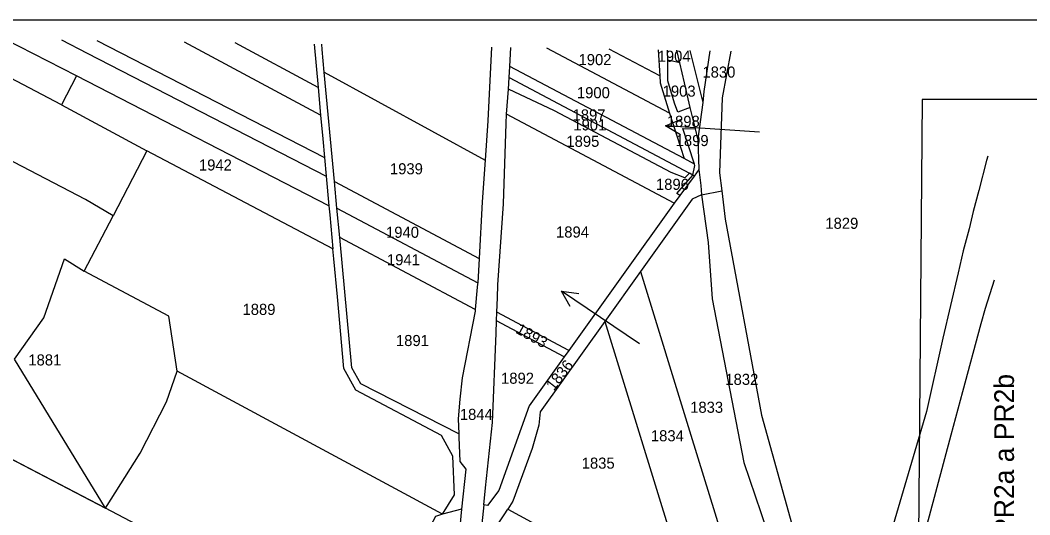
# Model space of a CAD drawing. Extents: x -584305 to -582773, y -1166873 to -1164754.
# Drawn here: x -583983 to -583345, y -1165085 to -1164773 of the extents above; entities that cross this region are included whole.
import ezdxf

# ---------------------------------------------------------------- set-up
doc = ezdxf.new("R2010")
doc.units = 0
for name, color, linetype in [('37', 7, 'Continuous'), ('_Rám HC11-R', 7, 'Continuous'), ('Hranice parcel', 7, 'Continuous'), ('Parcelní čísla', 7, 'Continuous')]:
    doc.layers.add(name, color=color, linetype=linetype)

msp = doc.modelspace()

# ---------------------------------------------------------------- linework, layer by layer
at = {"layer": '37'}
for p, q in [((-583515.54, -1164843.77), (-583574.89, -1164839.89)), ((-583591.27, -1164977.57), (-583640.58, -1164944.31))]:
    msp.add_line(p, q, dxfattribs=at)
for points in [[(-583565.32, -1164845.48), (-583574.89, -1164839.89), (-583564.68, -1164835.59)], [(-583635.14, -1164953.96), (-583640.58, -1164944.31), (-583629.59, -1164945.74)]]:
    msp.add_lwpolyline(points, dxfattribs=at)
at = {"layer": '_Rám HC11-R'}
for p, q in [((-583412.61, -1164823.12), (-583417.05, -1165365.82)), ((-583171.08, -1164823.12), (-583412.61, -1164823.12))]:
    msp.add_line(p, q, dxfattribs=at)
msp.add_lwpolyline([(-582820.03, -1166873.12), (-582820.03, -1164773.12), (-584305.03, -1164773.12), (-584305.03, -1166873.12), (-582820.03, -1166873.12)], dxfattribs=at)
msp.add_lwpolyline([(-583928.98, -1165081.35), (-583986.49, -1164987.28), (-583967.99, -1164961.13), (-583954.85, -1164923.82), (-583942.36, -1164931.66), (-583924.13, -1164896.6), (-583941.58, -1164886.27), (-584101.83, -1164802.98), (-584094.81, -1164829.69), (-584009.27, -1164870.93), (-583995.35, -1164891.63), (-584020.43, -1164938.66), (-584028.48, -1164951.62), (-584035.7, -1164958.26), (-584055.06, -1164973.28), (-584042.99, -1165013.09), (-584037.3, -1165024.95)], close=True, dxfattribs=at)
at = {"layer": 'Hranice parcel'}
for p, q in [((-583956.67, -1164826.46), (-584037.5, -1164784.25)), ((-583947.23, -1164808.23), (-583992.46, -1164785)), ((-583797.07, -1164788.27), (-583794.55, -1164815.59)), ((-583673.36, -1164802.36), (-583672.59, -1164790.35)), ((-583572.27, -1164831.74), (-583650, -1164790.72)), ((-583578.48, -1164808.32), (-583610.56, -1164791.38)), ((-583573.5, -1164798.45), (-583573.59, -1164792)), ((-583565.79, -1164800.08), (-583567.76, -1164792.1)), ((-583559.42, -1164792.24), (-583551.21, -1164825.14)), ((-583565.79, -1164800.08), (-583573.5, -1164798.45)), ((-583790.62, -1164805.87), (-583688.95, -1164861.53)), ((-583784.14, -1164875.08), (-583790.62, -1164805.87)), ((-583673.81, -1164809.27), (-583673.36, -1164802.36)), ((-583563.17, -1164860.53), (-583673.36, -1164802.36)), ((-583947.23, -1164808.23), (-583956.67, -1164826.46)), ((-583787.65, -1164890.27), (-583947.23, -1164808.23)), ((-583674.2, -1164816.62), (-583673.81, -1164809.27)), ((-583673.81, -1164809.27), (-583559.73, -1164869.75)), ((-583794.55, -1164815.59), (-583792.92, -1164833.12)), ((-583675.3, -1164832.56), (-583674.2, -1164816.62)), ((-583551.21, -1164825.14), (-583554.55, -1164848.01)), ((-583956.67, -1164826.46), (-583902.79, -1164855.56)), ((-583556.01, -1164841.8), (-583559.26, -1164828.28)), ((-583569.45, -1164888.74), (-583675.3, -1164832.56)), ((-583572.27, -1164831.74), (-583563.17, -1164860.53)), ((-583554.55, -1164848.01), (-583556.01, -1164841.8)), ((-583554.55, -1164848.01), (-583553.72, -1164867.31)), ((-583902.79, -1164855.56), (-583924.13, -1164896.6)), ((-583785.12, -1164917.52), (-583902.79, -1164855.56)), ((-583790.48, -1164859.88), (-583789.39, -1164871.59)), ((-583556.62, -1164863.99), (-583563.17, -1164860.53)), ((-583557.54, -1164871.02), (-583559.73, -1164869.75)), ((-583553.72, -1164867.31), (-583556.82, -1164871.54)), ((-583789.39, -1164871.59), (-583787.65, -1164890.27)), ((-583784.14, -1164875.08), (-583692.74, -1164923.53)), ((-583782.59, -1164891.76), (-583784.14, -1164875.08)), ((-583556.82, -1164871.54), (-583565.83, -1164883.81)), ((-583556.82, -1164871.54), (-583557.54, -1164871.02)), ((-583552.19, -1164883.47), (-583539.33, -1164880.91)), ((-583569.45, -1164888.74), (-583635.97, -1164981.63)), ((-583565.83, -1164883.81), (-583569.45, -1164888.74)), ((-583782.59, -1164891.76), (-583693.61, -1164938.95)), ((-583780.85, -1164910.42), (-583782.59, -1164891.76)), ((-583695.22, -1164955.87), (-583780.85, -1164910.42)), ((-583692.74, -1164923.53), (-583693.61, -1164938.95)), ((-583590.65, -1164931.88), (-583613.28, -1164963.32)), ((-583681.73, -1164963.03), (-583681.51, -1164957.46)), ((-583635.97, -1164981.63), (-583681.51, -1164957.46)), ((-583638.91, -1164985.75), (-583681.73, -1164963.03)), ((-583613.28, -1164963.32), (-583555.31, -1165151.49)), ((-583635.97, -1164981.63), (-583638.91, -1164985.75)), ((-583715.82, -1165085.15), (-583883.69, -1164994.71)), ((-583928.98, -1165081.35), (-584037.3, -1165024.95)), ((-583775.78, -1165161.12), (-583928.98, -1165081.35)), ((-583703.81, -1165081.91), (-583715.82, -1165085.15))]:
    msp.add_line(p, q, dxfattribs=at)
for points in [[(-583956.79, -1164785.6), (-583940.44, -1164794), (-583789.39, -1164871.59)], [(-583934.36, -1164785.97), (-583790.48, -1164859.88)], [(-583792.92, -1164833.12), (-583878.86, -1164786.9)], [(-583794.55, -1164815.59), (-583846.83, -1164787.44)], [(-583790.62, -1164805.87), (-583791.96, -1164791.62), (-583792.12, -1164788.35)], [(-583684.95, -1164790.14), (-583687.26, -1164836.6), (-583688.95, -1164861.53)], [(-583579.46, -1164791.9), (-583578.48, -1164808.32)], [(-583546.92, -1164792.45), (-583550.7, -1164818.16), (-583551.21, -1164825.14)], [(-583533.66, -1164792.67), (-583539, -1164822.23), (-583540.65, -1164869.56), (-583539.33, -1164880.91)], [(-583559.26, -1164828.28), (-583567.15, -1164831.18), (-583569.14, -1164825.6), (-583573.36, -1164811.31), (-583573.5, -1164798.45)], [(-583924.13, -1164896.6), (-583941.58, -1164886.27), (-584101.83, -1164802.98)], [(-583559.26, -1164828.28), (-583562.84, -1164812.68), (-583565.79, -1164800.08)], [(-583578.48, -1164808.32), (-583578.32, -1164812.61), (-583572.27, -1164831.74)], [(-583559.73, -1164869.75), (-583562.76, -1164872.64), (-583571.41, -1164869.32), (-583645.1, -1164830.32), (-583674.2, -1164816.62)], [(-583792.92, -1164833.12), (-583791.53, -1164848.13), (-583790.48, -1164859.88)], [(-583681.51, -1164957.46), (-583681.15, -1164948.55), (-583680.82, -1164940.23), (-583677.33, -1164889.12), (-583675.68, -1164838.44), (-583675.3, -1164832.56)], [(-583556.62, -1164863.99), (-583563.92, -1164841.61), (-583556.01, -1164841.8)], [(-583688.95, -1164861.53), (-583690.72, -1164887.86), (-583692.74, -1164923.53)], [(-583371.1, -1164859.09), (-583371.94, -1164861.81), (-583376.89, -1164880.69), (-583380.48, -1164894.04), (-583383.01, -1164904.79), (-583386.64, -1164918.76), (-583389.86, -1164932.59), (-583399.53, -1164973.87), (-583409.9, -1165020.19), (-583432.04, -1165095.47), (-583443.57, -1165131.51), (-583453.55, -1165161.91), (-583460.36, -1165183.86), (-583462.37, -1165189.75)], [(-583557.54, -1164871.02), (-583556.31, -1164864.93), (-583556.62, -1164863.99)], [(-583553.72, -1164867.31), (-583552.63, -1164877.54), (-583552.19, -1164883.47)], [(-583565.83, -1164883.81), (-583567.66, -1164882.67), (-583557.54, -1164871.02)], [(-583539.33, -1164880.91), (-583537.25, -1164898.81), (-583514.28, -1165022.56), (-583492.96, -1165098.9), (-583477.86, -1165141.87), (-583468.08, -1165182.16), (-583462.37, -1165189.75)], [(-583552.19, -1164883.47), (-583557.98, -1164886.17), (-583590.65, -1164931.88)], [(-583552.19, -1164883.47), (-583548.02, -1164913.48), (-583545.31, -1164949.05), (-583525.33, -1165052.37), (-583514.66, -1165083.97), (-583500.34, -1165127.02), (-583480.63, -1165192.3)], [(-583787.65, -1164890.27), (-583787.1, -1164896.07), (-583785.12, -1164917.52)], [(-583883.69, -1164994.71), (-583888.8, -1164960.1), (-583942.36, -1164931.66), (-583924.13, -1164896.6)], [(-583705.57, -1165034.36), (-583767.43, -1165002.87), (-583773.16, -1164992.64), (-583780.85, -1164910.42)], [(-583715.82, -1165085.15), (-583708.38, -1165072.99), (-583709.25, -1165048.51), (-583716.57, -1165035.37), (-583770.55, -1165006.73), (-583778.14, -1164993.11), (-583782.32, -1164947.82), (-583784.54, -1164923.87), (-583785.12, -1164917.52)], [(-583590.65, -1164931.88), (-583558.79, -1165035.3), (-583516.2, -1165173.54)], [(-583693.61, -1164938.95), (-583693.66, -1164939.83), (-583693.85, -1164941.8), (-583695.22, -1164955.87)], [(-583419.03, -1165126.58), (-583408.09, -1165086.08), (-583394.27, -1165034.92), (-583386.86, -1165007.52), (-583375.3, -1164964.75), (-583372.66, -1164954.97), (-583366.85, -1164937.17)], [(-583695.22, -1164955.87), (-583695.31, -1164956.85), (-583703.37, -1164998.89), (-583704.97, -1165012.52), (-583705.89, -1165024.84), (-583705.57, -1165034.36)], [(-583689.69, -1165079.18), (-583688.59, -1165068.55), (-583684.31, -1165027.11), (-583682.04, -1164970.72), (-583681.73, -1164963.03)], [(-583613.28, -1164963.32), (-583654.06, -1165020.55), (-583654.94, -1165028.84), (-583659.2, -1165043.56), (-583671.34, -1165076.83), (-583674.6, -1165081.96)], [(-583638.91, -1164985.75), (-583660.97, -1165016.57), (-583680.35, -1165070.13), (-583687.37, -1165079.52), (-583689.69, -1165079.18)], [(-583928.98, -1165081.35), (-583906.94, -1165046.62), (-583890.26, -1165014.23), (-583883.69, -1164994.71)], [(-583705.57, -1165034.36), (-583705.48, -1165036.51), (-583704.93, -1165051.8), (-583701.09, -1165056.68), (-583703.81, -1165081.91)], [(-583689.69, -1165079.18), (-583692.29, -1165103.21), (-583695.31, -1165125.06)], [(-583703.81, -1165081.91), (-583705.01, -1165093.13), (-583708.16, -1165119.58), (-583711.05, -1165144.58), (-583717.84, -1165183.67), (-583722.66, -1165203.37), (-583727.49, -1165223.07), (-583744.1, -1165275.81), (-583757.13, -1165315.32), (-583766.76, -1165339.34), (-583776.4, -1165363.37), (-583796.44, -1165401.06), (-583808.59, -1165430.5)], [(-583715.82, -1165085.15), (-583720.31, -1165086.49), (-583725.1, -1165095.68), (-583717.77, -1165126.09), (-583718, -1165140.48), (-583723.12, -1165165.52), (-583727.43, -1165186.55)], [(-583682.27, -1165093.64), (-583676.8, -1165085.62), (-583674.6, -1165081.96)], [(-583674.6, -1165081.96), (-583659.91, -1165089.88), (-583621.9, -1165114.45), (-583555.31, -1165151.49)]]:
    msp.add_lwpolyline(points, dxfattribs=at)

# ---------------------------------------------------------------- texts
at = {"layer": '_Rám HC11-R'}
msp.add_text('SO 01 Průleh PR2a a PR2b', height=12.5, rotation=90, dxfattribs=at).set_placement((-583354.57, -1165203.76))
at = {"layer": 'Parcelní čísla'}
for s, p in [('1904', (-583579.84, -1164799.36)), ('1902', (-583629.87, -1164801.51)), ('1830', (-583551.54, -1164809.37)), ('1900', (-583630.9, -1164822.4)), ('1903', (-583576.68, -1164821.4)), ('1897', (-583633.63, -1164836.43)), ('1901', (-583633.13, -1164842.72)), ('1898', (-583574.04, -1164840.49)), ('1895', (-583637.54, -1164853.1)), ('1899', (-583568.46, -1164852.61)), ('1942', (-583869.85, -1164868.05)), ('1939', (-583749.08, -1164870.46)), ('1896', (-583580.92, -1164880.27)), ('1829', (-583473.83, -1164904.88)), ('1940', (-583751.55, -1164910.55)), ('1894', (-583644.09, -1164910.39)), ('1941', (-583750.98, -1164927.89)), ('1889', (-583842.29, -1164959.24)), ('1891', (-583745.28, -1164978.92)), ('1881', (-583977.68, -1164991.18)), ('1892', (-583678.86, -1165002.74)), ('1832', (-583537.04, -1165003.45)), ('1833', (-583559.29, -1165021.09)), ('1844', (-583704.89, -1165025.58)), ('1834', (-583584.12, -1165039.07)), ('1835', (-583627.85, -1165056.36))]:
    msp.add_text(s, height=7, dxfattribs=at).set_placement(p)
for s, rotation, p in [('1893', 331, (-583670.18, -1164970.32)), ('1836', 52, (-583645.5, -1165007.58))]:
    msp.add_text(s, height=7, rotation=rotation, dxfattribs=at).set_placement(p)

doc.saveas('drawing.dxf')
